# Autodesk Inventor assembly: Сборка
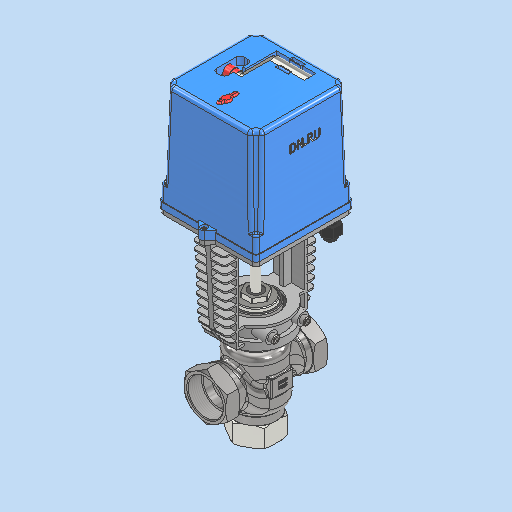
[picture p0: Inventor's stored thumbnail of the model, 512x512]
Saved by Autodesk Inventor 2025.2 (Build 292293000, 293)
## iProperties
Created: 2026-04
Part Number: Сборка
Document SubType Name: Assembly
Designer: igorr
Author: igorr
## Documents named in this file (7)
- D:\PROJECT CAD\DN.RU\...197(ACTUALE). VRg3M-S-31M-PED-T Клапан регулирующий трехходовой DN.ru\Исходники\DN40\Сборка.iam
- D:\PROJECT CAD\DN.RU\...197(ACTUALE). VRg3M-S-31M-PED-T Клапан регулирующий трехходовой DN.ru\Исходники\DN40\Деталь 1.ipt
- D:\PROJECT CAD\DN.RU\...197(ACTUALE). VRg3M-S-31M-PED-T Клапан регулирующий трехходовой DN.ru\Исходники\DN40\Деталь 2.ipt
- D:\PROJECT CAD\DN.RU\...197(ACTUALE). VRg3M-S-31M-PED-T Клапан регулирующий трехходовой DN.ru\Исходники\DN40\Деталь 3.ipt
- C:\Users\igorr\OneDrive\Документы\Inventor\Content Center Files\R2025\ru-RU\AS 1421(2)\AS 1421 - M10 x 12 засверленный конец.ipt
- C:\Users\igorr\OneDrive\Документы\Inventor\Content Center Files\R2025\ru-RU\AS 1420\AS 1420 - 1973 - M5 x 10.ipt
- C:\Users\igorr\OneDrive\Документы\Inventor\Content Center Files\R2025\ru-RU\AS 1427(05)\AS 1427 - M3 x 8(5) II.ipt
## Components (9 placed, 6 different names)
1. Деталь 1:1 — Касательность:1, Касательность:2, Угол:1, Совмещение:1, Совмещение:5, Угол:3, Совмещение:8, Совмещение:10, Совмещение:11
2. Деталь 2:1 — Касательность:1, Касательность:2, Угол:1, Совмещение:1
3. Деталь 3:1 — Совмещение:2, Совмещение:3, Угол:2, Совмещение:5, Угол:3, Совмещение:11
4. AS 1420 - метрическая M5 x 10:1 — Совмещение:8
5. AS 1420 - метрическая M5 x 10:2 — Совмещение:10
6. AS 1427 H - метрическая M3 x 8:1
7. AS 1427 H - метрическая M3 x 8:2
8. AS 1421 засверленный конец - метрическая M10 x 12 засверленный конец:1 — Заподлицо:1
9. AS 1421 засверленный конец - метрическая M10 x 12 засверленный конец:2 — Заподлицо:1
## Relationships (13: Mate 7, Angle 3, Tangent 2, Flush 1)
- Касательность:1 [Tangent]: Деталь 1:1 ↔ Деталь 2:1
- Касательность:2 [Tangent]: Деталь 1:1 ↔ Деталь 2:1
- Угол:1 [Angle]: Деталь 1:1 ↔ Деталь 2:1
- Совмещение:1 [Mate]: Деталь 1:1 ↔ Деталь 2:1
- Совмещение:2 [Mate]: Деталь 3:1
- Совмещение:3 [Mate]: Деталь 3:1
- Угол:2 [Angle]: Деталь 3:1
- Совмещение:5 [Mate]: Деталь 1:1 ↔ Деталь 3:1
- Угол:3 [Angle]: Деталь 1:1 ↔ Деталь 3:1
- Совмещение:8 [Mate]: Деталь 1:1 ↔ AS 1420 - метрическая M5 x 10:1
- Совмещение:10 [Mate]: Деталь 1:1 ↔ AS 1420 - метрическая M5 x 10:2
- Совмещение:11 [Mate]: Деталь 1:1 ↔ Деталь 3:1
- Заподлицо:1 [Flush]: AS 1421 засверленный конец - метрическая M10 x 12 засверленный конец:1 ↔ AS 1421 засверленный конец - метрическая M10 x 12 засверленный конец:2
